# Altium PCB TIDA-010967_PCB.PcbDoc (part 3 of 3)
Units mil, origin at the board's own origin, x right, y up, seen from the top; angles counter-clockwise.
Board outline 2322.7 x 960 mil, 2 copper layers (Top Layer, Bottom Layer), stack 44.731 mil thick; 178 components, 80 nets, 496 pads, 399 vias.
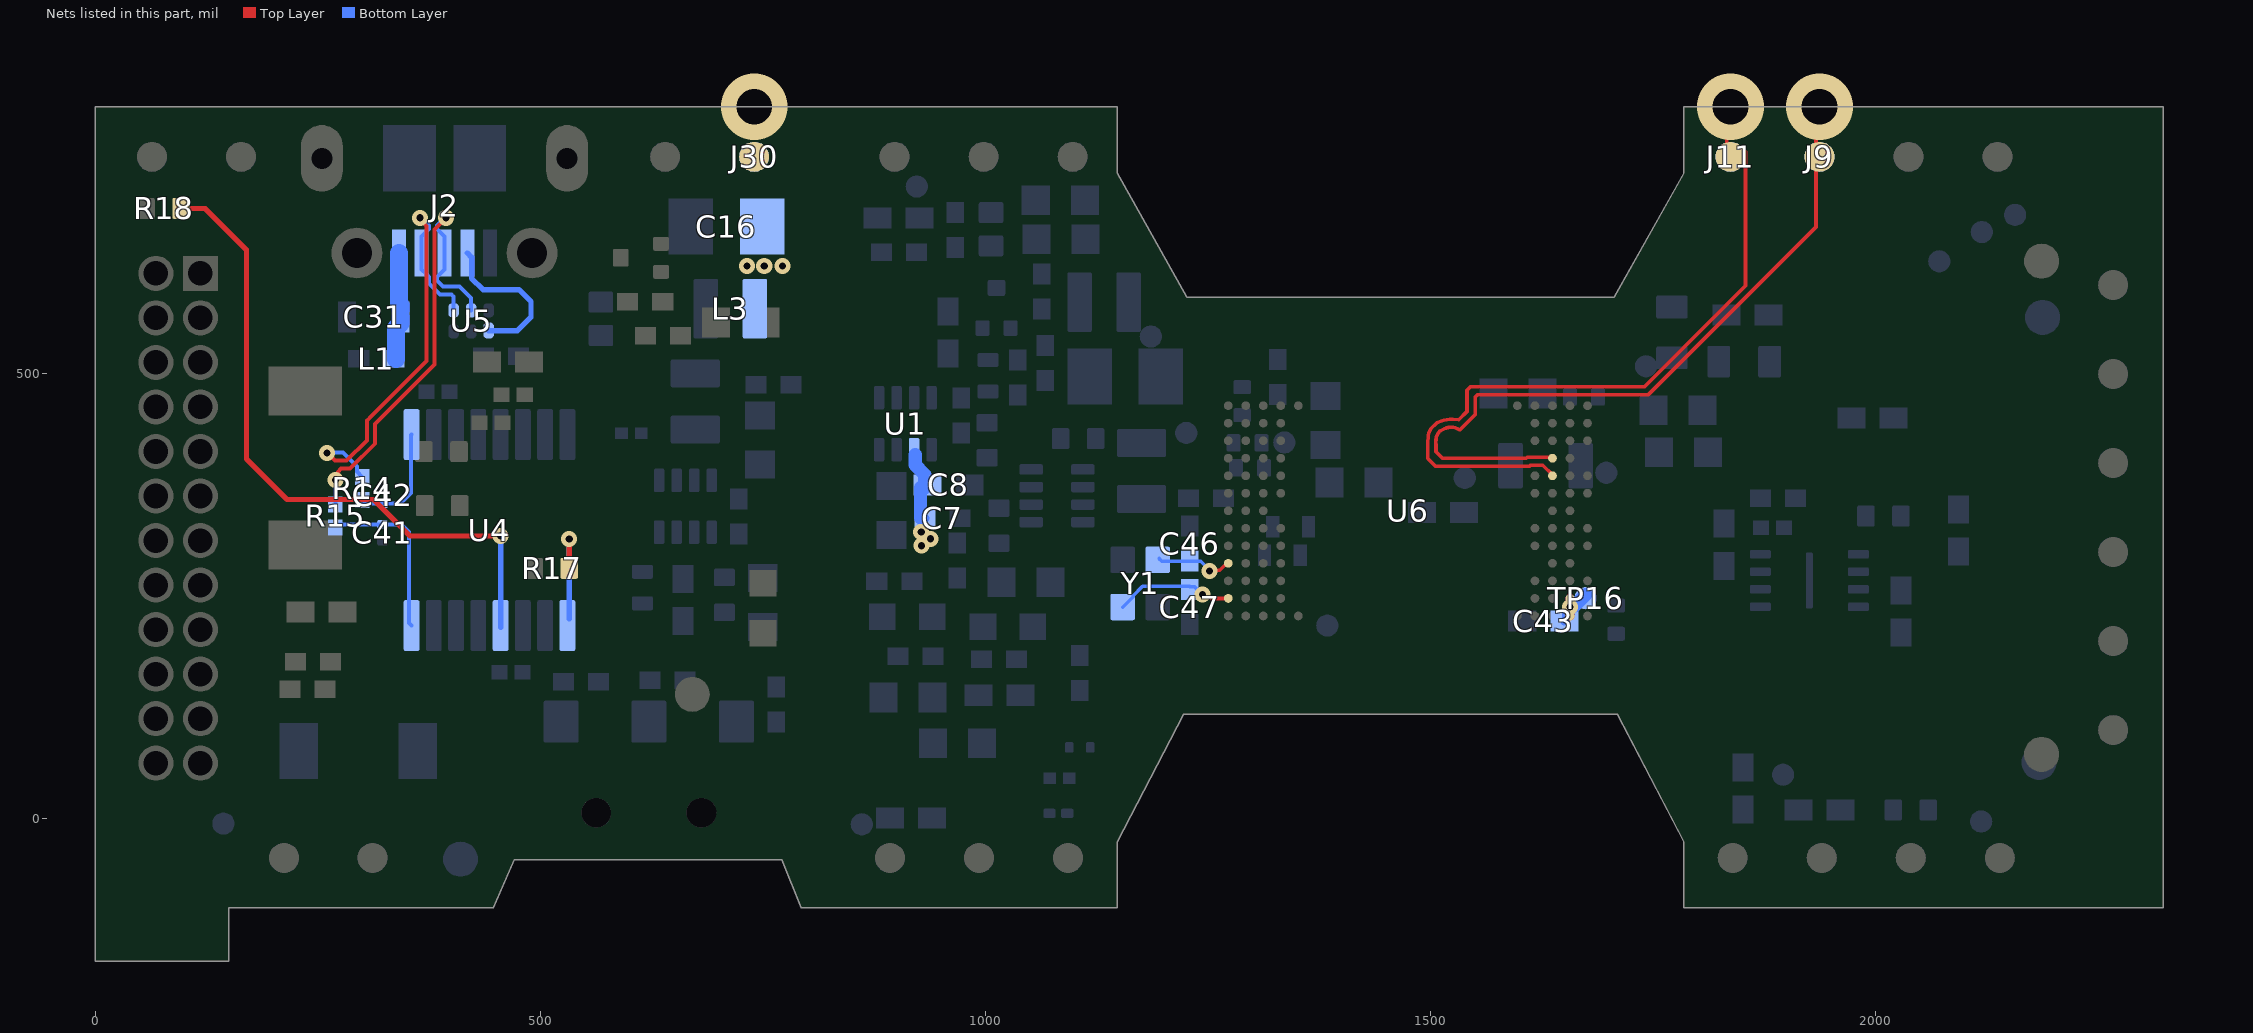
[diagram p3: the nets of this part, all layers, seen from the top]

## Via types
v1: diameter 18, hole 8, Top Layer to Bottom Layer, tented both sides, 370 vias
v2: diameter 75, hole 40, Top Layer to Bottom Layer, 26 vias
v3: diameter 118.11, hole 118.11, Top Layer to Bottom Layer, tented both sides, 3 vias

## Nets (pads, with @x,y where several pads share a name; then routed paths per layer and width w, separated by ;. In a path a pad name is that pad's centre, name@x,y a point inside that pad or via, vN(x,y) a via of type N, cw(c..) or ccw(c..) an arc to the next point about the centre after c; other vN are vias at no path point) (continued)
UART_RX: R18.2 U4.4 | length 751.9
  Top Layer w6: R18.2@96.28,685.75 123.3,685.75 169.77,639.28 169.77,404.28 215.3,358.76 312.41,358.76 353.34,317.83 v1(455.27,317.83)
  Bottom Layer w6: U4.4@455.22,215.01 455.22,317.79 v1(455.27,317.83)
UART_TX: R17.2 U4.1 | length 127.5
  Top Layer w6: R17.2@532.28,281.48 v1(532.28,314.31)
  Bottom Layer w6: v1@530.47,310.91 v1@532.28,312.72 ; U4.1@532.28,224.8 v1@532.28,312.72 ; v1(532.28,314.31) v1@532.28,312.72 ; v1@534.15,314.59 v1@532.28,312.72
UARTA_RX: J11.1 U6.J3 | length 823.4
  Top Layer w4: U6.J3@1636.7,385.49 1636.7,386.44 1625.73,397.41 1612.08,397.41 1610.97,396.3 1505.25,396.3 1496.65,404.9 1496.65,418.75 1496.66,422.97 cw(c1522.66,422.94) 1497,427.16 1497.29,429.55 1497.29,431.02 1497.73,433.18 1500.04,438.15 1506.71,444.82 1512.87,447.12 1514.85,447.74 cw(c1522.66,422.94) 1524.43,448.88 1531.56,448.39 1540.75,457.58 1540.75,481.55 1544.86,485.67 1740.26,485.67 1853.55,598.95 1853.55,749.18 1853.44,749.28 ; J11.1@1832.7,743.75 v2@1832.7,800
  other v2: 1836.65,800
UARTA_TX: J9.1 U6.K3 | length 825.4
  Top Layer w4: U6.K3@1636.27,405.12 1635.1,406.29 1631.56,406.29 1631.44,406.41 1608.35,406.41 1607.24,405.3 1513.17,405.3 1507.08,411.39 1505.91,412.56 1505.91,420 cw(c1522.66,422.94) 1505.91,425.87 1506.29,429.01 1508.43,433.58 1509.04,434.42 1510.44,435.82 1515.01,438.12 cw(c1522.66,422.94) 1532.15,437.04 1532.58,437.04 1532.94,437.05 1549.75,453.85 1549.75,473.68 1552.73,476.67 1744.5,476.67 1932.74,664.9 1932.74,743.75 1932.74,796.09 v2(1936.65,800)
USB_5V: C31.2 J2.1 L1.1 | length 117.3
  Bottom Layer w15: L1.1@335.25,516.74 L1.1@337.06,518.55
  Bottom Layer w20: L1.1@337.74,516.29 337.74,551.37 342.8,556.43 C31.2@342.8,563.93 ; J2.1@341.05,635.69 341.05,579.04 342.8,577.29 C31.2@342.8,571.43
USB_DM: J2.2 R14.1 U5.4 | length 527.7
  Top Layer w4.5: v1(260.3,411.23) 269.14,402.39 282.29,402.39 305.06,425.16 305.06,447.27 310.33,452.54 371.92,514.13 371.92,666.05 364.83,673.14 v1(364.83,675.22)
  Bottom Layer w4.5: v1(260.3,411.23) 260.71,411.64 278.3,411.64 293.82,396.12 293.82,390.12 R14.1@299.76,384.18 ; v1(364.83,675.22) 366.14,675.22 374.93,666.42 374.93,662.69 366.64,654.4 366.64,616.99 372.26,611.37 374.93,608.73 374.93,601.28 387.03,589.18 399.8,589.18 402.43,586.55 U5.4@402.43,571.28
USB_DP: J2.3 R15.1 U5.5 | length 521.6
  Top Layer w4.5: v1(269.92,380.89) 272.5,383.47 272.5,389.93 275.96,393.39 286.02,393.39 314.06,421.43 314.06,443.54 380.92,510.4 380.92,662.12 v1(394.05,675.27)
  Bottom Layer w4.5: R15.1@269.37,353.37 269.92,353.92 v1(269.92,380.89) ; v1(394.05,675.27) 392.79,675.27 383.93,666.42 383.93,662.69 392.23,654.4 J2.3@392.23,635.69 392.23,616.99 386.6,611.37 383.93,608.73 383.93,605.01 390.76,598.18 403.53,598.18 403.6,598.11 408.8,598.11 421.78,585.13 421.78,571.62 U5.5@422.12,571.28
USB_ID: J2.4 U5.1 | length 179.5
  Bottom Layer w6: J2.4@417.82,635.69 422.69,630.82 422.69,607.22 435.41,594.5 475.94,594.5 489.4,581.04 489.4,563.6 474.29,548.49 U5.1@441.66,548.49
USB_INPUT_3V3: C7.1 C8.2 C16.1 J30.1 L3.2 U1.6 | length 79.1
  Bottom Layer w10: C7.1@929,340.58 C7.1@931.83,337.76
  Bottom Layer w15: U1.6@920.94,409.06 920.94,397.52 931.82,386.65 C8.2@931.82,372.19 ; C7.1@926.81,338.48 C8.2@926.81,372.19
  other v1: 927.83,306.91 938.28,314.7 927.69,322.19 732.02,621.26 751.37,621.26 771.92,621.02
  other v2: 740.07,800
USBDM: C42.2 R14.2 U4.9 | length 124.1
  Bottom Layer w4.5: R14.2@301.23,354.52 301.46,354.29 316.88,354.29 342.61,354.29 354.67,366.35 354.67,431.16 U4.9@355.24,431.73
USBDP: C41.2 R15.2 U4.8 | length 193.4
  Bottom Layer w4.5: R15.2@268.94,330.46 269.39,330.91 343.64,330.91 352.26,322.29 352.26,220.14 U4.8@355.24,217.16
VPP_1P7: C43.1 TP16.1 U6.A2 U6.B2 | length 55
  Top Layer w10: U6.A2@1656.39,228.01 U6.B2@1656.39,247.7
  Bottom Layer w10: C43.1@1650.04,222.13 1652.21,224.29 v1@1652.21,236.65
  Bottom Layer w15: v1@1659.85,238.02 TP16.1@1673.91,252.09
  other v1: 1656.45,238.02
XTALM: C47.2 U6.B10 Y1.1 | length 124.9
  Top Layer w4: v1@1251.82,249.38 1253.59,247.62 U6.B10@1272.35,247.62
  Bottom Layer w4: Y1.1@1153.95,237.93 1165.73,249.71 1165.73,250.86 1176.26,261.4 C47.2@1229.39,261.4 ; C47.2@1229.39,260.93 1234.67,260.93 v1(1243.54,252.06)
XTALP: C46.2 U6.D10 Y1.3 | length 88.3
  Top Layer w4: v1@1251,279.05 1251.25,279.3 1263.07,279.3 1271.01,287.24 U6.D10@1272.59,287.24
  Bottom Layer w4: Y1.3@1194.84,292.6 1197.97,289.47 1241.76,289.47 1251.42,279.81 v1(1251.42,278.38)
pads on no net: FID1.1 FID2.1 FID3.1 FID4.1 FID5.1 FID6.1 J1.5 J1.6 J1.7 J1.8 J1.10 J1.13 J1.14 J1.16 SW1. U4.2 U4.6 U4.7 U4.14 U4.15 U4.16 U6.L3 U6.L4
copper on no net:
  other v3: 75.87,-88.15 2251.57,-27.28 2251.07,726.6

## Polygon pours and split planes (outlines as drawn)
RADAR_1V2 on Bottom Layer "RADAR_1V2_L02_P039" (solid, remove dead copper, pour order 39): 1664.37,427.66 1697.77,427.66 1723.65,427.66 1723.65,413.87 1713.96,404.19 1713.96,370.84 1652.34,370.84 1652.34,420.62
REG_3V3 on Bottom Layer "REG_3V3_L02_P033" (solid, remove dead copper, pour order 33): 904.81,277.66 904.81,257.51 923.51,238.8 923.51,66.76 960.5,66.76 960.5,103.72 976.09,121.77 1013.61,121.98 1013.61,168.41 1013.61,217.62 1017.87,221.87 1017.87,259.62 1035.08,276.82 1035.08,301.5 1065.88,301.5 1065.88,340.97 999.28,340.97 999.28,324.45 952.48,277.66
SW3_3V3 on Bottom Layer "SW3_3V3_L02_P044" (solid, remove dead copper, pour order 44): 643.65,455.15 702.69,455.15 702.69,419.41 692.56,419.41 678.9,405.75 678.9,366.52 665.96,366.52 665.96,405.49 652.04,419.41 643.74,419.41
RADAR_1V8 on Bottom Layer "RADAR_1V8_L02_P041" (solid, remove dead copper, pour order 41): 1356.54,488.31 1317.87,488.31 1317.87,467.23 1277.53,467.23 1277.53,443.63 1347.92,443.63 1356.72,452.43
GND on Bottom Layer "GND_L02_P061" (solid, remove dead copper, pour order 61): -7.41,800 -7.41,-160 2315.29,-160 2315.29,800
USB_INPUT_3V3 on Bottom Layer "USB_INPUT_3V3_L02_P058" (solid, remove dead copper, pour order 58): 917.62,388.33 917.62,303.4 923.44,297.58 949.01,297.58 949.01,388.33
REG_1V8 on Bottom Layer "REG_1V8_L02_P057" (solid, remove dead copper, pour order 57): 1146.03,616.54 1145.78,616.29 1145.78,543.21 1146.78,543.21 1169.47,520.51 1169.47,465.64 1225.85,465.64 1225.85,532.48 1212.91,532.48 1193.17,552.23 1193.17,560.79 1175.96,578 1175.96,616.29
REG_OUT_1V8 on Bottom Layer "REG_OUT_1V8_L02_P055" (solid, remove dead copper, pour order 55): 1090.32,667.74 1091.63,666.43 1091.63,545.6 1125.97,545.6 1130.43,550.05 1130.43,668
REG_OUT_1V8 on Bottom Layer "REG_OUT_1V8_L02_P054" (solid, remove dead copper, pour order 54): 1112.86,445.86 1112.86,406.14 1203.76,406.14 1204.2,406.59 1204.05,406.74 1204.05,446.01
DC_OUT_3V3 on Bottom Layer "DC_OUT_3V3_L02_P045" (solid, remove dead copper, pour order 45): 673.34,608.75 708.65,608.75 708.65,532.93 763.79,477.79 763.79,432.56 724.94,432.56 724.94,451.57 701.6,474.91 642.9,474.91 642.9,578.31
5V_IN_USB on Bottom Layer "5V_IN_USB_L02_P043" (solid, remove dead copper, pour order 43): 736.55,335.44 686.1,335.48 686.1,305.78 719.48,305.78 730,295.26 730,265.43 712.75,248.18 693.24,248.18 693.24,224.84 694.04,224.04 718.81,224.04 718.81,226.28 739.2,246.67 767.88,246.67 767.88,307.08
NetD1_2 on Bottom Layer "NETD1_2_L02_P052" (solid, remove dead copper, pour order 52): 192.27,526.97 311.02,526.97 311.02,497.52 191.97,497.52
USB_INPUT_3V3 on Bottom Layer "USB_INPUT_3V3_L02_P046" (solid, remove dead copper, pour order 46): 723.31,752.95 723.31,534.79 768.85,534.79 782.08,548.02 782.08,752.23
RADAR_1P2_RF on Bottom Layer "RADAR_1P2_RF_L02_P031" (solid, remove dead copper, pour order 31): 1302.05,438.29 1399.72,438.29 1399.72,403.58 1357.84,403.58 1349.45,411.97 1302.19,411.97
RADAR_1V_RF_OUT on Bottom Layer "RADAR_1V_RF_OUT_L02_P032" (solid, remove dead copper, pour order 32): 1305.23,404.9 1305.62,404.51 1349.32,404.51 1359.13,394.69 1400.25,394.69 1400.25,360.47 1363.84,360.47 1340.07,384.24 1305.42,384.24
RADAR_SRAM_1V2 on Bottom Layer "RADAR_SRAM_1V2_L02_P038" (solid, remove dead copper, pour order 38): 1666.18,494.66 1596.91,494.66 1596.91,456.88 1636.7,456.88 1636.7,444.17 1666.55,444.17
SW3_1V8 on Bottom Layer "SW3_1V8_L02_P034" (solid, remove dead copper, pour order 34): 1095.35,359.82 1095.35,345.85 1143.77,345.85 1147.96,341.66 1205.92,341.66 1205.92,375.92 1205.05,376.78 1142.61,376.78 1125.77,359.95
5V_IN_USB on Bottom Layer "5V_IN_USB_L02_P028" (solid, remove dead copper, pour order 28): 193.18,-45.67 252.18,-45.67 252.18,153.48 252.18,209.9 193.18,209.9
USB_INPUT_3V3 on Top Layer "USB_INPUT_3V3_L01_P049" (solid, remove dead copper, pour order 49): 721.81,632.03 855.98,632.03 878.57,609.44 878.57,429.5 947.48,360.6 947.48,296.98 915.56,296.98 915.56,332.21 848.32,399.45 848.32,415.17 832.22,432.14 831.87,464.05 845.23,479.12 845.23,602.32 721.81,602.92
5V_IN_USB on Top Layer "5V_IN_USB_L01_P042" (solid, remove dead copper, pour order 42): 233.71,150.17 233.79,150.1 233.79,126.72 519.92,126.72 703.07,309.87 771.2,309.87 771.2,245.48 694.18,245.48 548.84,100.14 192.4,100.14 192.4,154.19
GND on Top Layer "GND_L01_P063" (solid, remove dead copper, pour order 63): 1598,469.39 1597.76,469.15 1558.07,469.15 1558.07,451.58 1558.07,425 1589.1,425 1589.7,424.4 1601.01,435.71 1601.01,469.27 1601.49,469.75
GND on Top Layer "GND_L01_P060" (solid, remove dead copper, pour order 60): 0,800 0,-160 2322.7,-160 2322.7,800
NetD1_2 on Top Layer "NETD1_2_L01_P053" (solid, remove dead copper, pour order 53): 192.12,528.15 281.04,528.15 281.04,452.91 191.46,452.91
REG_OUT_1V8 on Top Layer "REG_OUT_1V8_L01_P056" (solid, remove dead copper, pour order 56): 1125.82,405.53 1154.54,405.53 1154.54,529.88 1128.85,555.56 1128.85,632.62 1092.16,632.62 1092.94,631.83 1092.94,534.94 1126.85,501.04
DC_OUT_3V3 on Top Layer "DC_OUT_3V3_L01_P050" (solid, remove dead copper, pour order 50): 715.26,575.16 715.26,510.03 643.41,510.03 643.41,551.13 667.44,575.16
5V_IN_USB on Top Layer "5V_IN_USB_L01_P029" (solid, remove dead copper, pour order 29): 191.82,331.69 191.82,220.19 191.82,105.06 236.91,105.06 237.19,105.35 237.19,180.21 251.51,194.53 251.51,246.4 285.68,280.57 285.68,331.12
RADAR_1V8 on Top Layer "RADAR_1V8_L01_P040" (solid, remove dead copper, pour order 40): 1264.21,474.23 1264.44,474 1264.44,456.58 1281.17,456.58 1281.51,456.92 1282.9,455.54 1282.9,438 1368.16,438 1368.16,474.11

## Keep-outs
Keep-Out Layer:
  text ".Layer_Name" at -1267.26,-2351.64 h60

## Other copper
Top Layer:
  text ".Layer_Name" at -1252.74,-2340.54 h60
Bottom Layer:
  pour cut-out: 1243.38,317.17 1239.29,313.08 1239.29,309.39 1246.08,309.39 1247.92,311.23 1247.92,315.34 1245.87,317.39
  text ".Layer_Name" at -1018.85,-2336.57 h60

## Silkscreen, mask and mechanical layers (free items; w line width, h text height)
Top Overlay:
  lines w10: 201.82,709.94 201.82,709.19 227.06,684.38
  text "RX   TX" at 1826,695.8 h18
  text "GND   3V3" at 611.39,690.75 h18
  text "3V3   GND  1V8" at 874.21,690.24 h18
  text "GPIO5  TCK" at 1993.97,682.42 h18
  text "TX RX" at 243.34,675.58 h18
  text "UARTA" at 1846.58,668.13 h18
  text "USB" at 719.63,661.86 h18
  text "TMS" at 2208.15,579.77 h18 r270
  text "GPIO2" at 2177.66,547.74 h18 r270
  text "SPI CS" at 2206.03,464.81 h18 r270
  text "I2C SDA" at 2177.66,451.19 h18 r270
  text "TEXAS" at 975.77,436.89 h20
  text "INSTRUMENTS" at 917.6,402.96 h20
  text "CLK" at 2209.22,324.65 h18 r270
  text "SCL" at 2177.34,319.13 h18 r270
  text "MOSI" at 2208.51,249.78 h18 r270
  text "MISO" at 2208.51,177.39 h18 r270
  text "For evaluation only;" at 1794.17,171.38 h35
  text "not FCC approved" at 1794.45,133.28 h35
  text "for resale." at 1792.61,96.14 h35
  text "TIDA-010967 Rev.B" at 1790.8,53.2 h40
  text "TDO" at 2009.56,15.69 h18
  text "REG" at 862.45,14 h18
  text "TX    RX  SOP0" at 1819.77,-9.19 h18
  text "5VDC  GND" at 178.77,-9.66 h18
  text "TDI" at 2116.52,-9.83 h18
  text "MODE  GND  NRST" at 862.04,-12.46 h18
  text ".Layer_Name" at -1264.57,-2344.88 h60
Bottom Overlay:
  lines w10: 604.88,307.14 604.88,306.95 614.44,297.39 626.93,297.39 ; 1186.01,583.92 1186.75,583.92 ; 1186.38,583.92 1220.65,549.64 1221.77,549.64 ; 1221.21,549.64 1230.84,549.46 ; 1589.25,443.79 1623.62,443.79
  text "FUNC" at 856.68,68.4 h23
  text "MODE" at 856.82,40.64 h23
  text "FLASHING MODE" at 465.67,4.19 h23
  text ".Layer_Name" at -1018.85,-2336.57 h25
Top Paste:
  text ".Layer_Name" at -1264.57,-2344.88 h60
Bottom Paste:
  text ".Layer_Name" at -1018.85,-2336.57 h60
Top Solder:
  text ".Layer_Name" at -1264.57,-2344.88 h60
  text ".Layer_Name" at -1264.57,-2344.88 h60
Bottom Solder:
  text ".Layer_Name" at -1018.85,-2336.57 h60
Drill Guide:
  text ".Layer_Name" at -1267.26,-2351.64 h60
M1 Board Outline:
  circle w2: c75.83,-88.16 r59.06
  circle w2: c2251.57,-27.15 r59.06
  circle w2: c2251.06,726.6 r59.06
  lines w2: 470.38,-45.81 771.2,-45.81 ; 470.42,-45.84 447,-100 150,-100 150,-160 0,-160 0,800 1147.72,800 1147.73,725.77 1225.82,586 1705.96,586 1784.42,725.77 1784.42,800 2322.7,800 2322.7,-100 1784.42,-100 1784.42,-25.77 1709.51,117.74 1222.67,117.74 1147.73,-25.77 1147.72,-100 793,-100 770.94,-45.67 ; 811.59,202.07 811.59,224.33 834.61,224.33 ; 811.64,202.02 834.66,202.02 ; 812.14,784.22 812.14,767.57 836.23,767.57 836.23,784.24 812.16,784.24 ; 834.66,202.17 834.66,224.29 ; 833,-85.22 833,-45.86 812.11,-45.86 812.11,-85.21 812.13,-85.23 833,-85.23 ; 833,-85.23 833,-85.23 ; 787.23,357.01 834.15,357.01 834.15,400.92 787.23,400.92 787.23,357.01 ; 810.44,486.64 834.74,486.64 834.74,516.84 810.44,516.84 810.44,486.64 ; 810.63,276.77 834.14,276.77 834.14,294.1 810.63,294.1 810.63,276.77 ; 811.87,574.1 835.25,574.1 835.25,589.41 811.9,589.41 811.87,574.1 ; 812.13,719.77 836.79,719.77 836.79,736.24 812.11,736.24 812.13,719.77 ; 814.24,9.72 830.96,9.72 830.96,23.86 814.24,23.86 814.24,9.72
  text ".Layer_Name" at -1273.87,-2274.95 h40
M3 3D STEP Top:
  lines w0.5: 685.19,-354.85 685.19,1023.11 ; 685.19,-354.85 724.56,-354.85 ; 685.19,-354.85 724.56,-354.85 ; 685.19,-354.85 685.19,-453.27 2161.56,-453.27 ; 685.19,1023.11 685.19,1160.9 2161.56,1160.9 ; 685.19,1023.11 724.56,1023.11 ; 685.19,1023.11 724.56,1023.11 ; 724.56,-354.85 ccw(c783.61,-354.85) 842.67,-354.85 ; 724.56,-354.85 cw(c783.61,-354.85) 825.37,-313.09 ; 724.56,-354.85 cw(c783.61,-354.85) 825.37,-313.09 ; 724.56,-354.85 ccw(c783.61,-354.85) 842.67,-354.85 ; 724.56,1023.11 ccw(c783.61,1023.11) 842.67,1023.11 ; 724.56,1023.11 cw(c783.61,1023.11) 842.67,1023.11 ; 724.56,1023.11 cw(c783.61,1023.11) 842.67,1023.11 ; 724.56,1023.11 ccw(c783.61,1023.11) 842.67,1023.11 ; 825.37,-313.09 cw(c783.61,-354.85) 842.67,-354.85 ; 825.37,-313.09 cw(c783.61,-354.85) 842.67,-354.85 ; 825.37,-313.09 882.04,-256.42 ; 825.37,-313.09 882.04,-256.42 ; 882.04,-256.42 882.04,924.68 2063.14,924.68 2063.14,-256.42 882.04,-256.42 ; 1452.59,314.13 1452.59,316.63 ; 1452.59,314.13 1490.09,314.13 ; 1452.59,314.13 1452.59,316.63 ; 1452.59,314.13 1490.09,314.13 ; 1452.59,316.63 1452.59,351.63 ; 1452.59,316.63 1453.59,316.63 ; 1452.59,316.63 1453.59,316.63 ; 1452.59,316.63 1452.59,351.63 ; 1452.59,316.63 1453.59,316.63 ; 1452.59,316.63 1453.59,316.63 ; 1452.59,351.63 1452.59,355.13 ; 1452.59,351.63 1453.59,351.63 ; 1452.59,351.63 1453.59,351.63 ; 1452.59,351.63 1452.59,355.13 ; 1452.59,351.63 1453.59,351.63 ; 1452.59,351.63 1453.59,351.63 ; 1452.59,355.13 1490.09,355.13 ; 1452.59,355.13 1490.09,355.13 ; 1453.59,316.63 cw(c1455.09,316.63) 1456.15,317.69 ; 1453.59,316.63 ccw(c1455.09,316.63) 1456.59,316.63 ; 1453.59,316.63 cw(c1455.09,316.63) 1456.15,317.69 ; 1453.59,316.63 ccw(c1455.09,316.63) 1456.59,316.63 ; 1453.59,351.63 cw(c1455.09,351.63) 1456.59,351.63 ; 1453.59,351.63 ccw(c1455.09,351.63) 1456.59,351.63 ; 1453.59,351.63 cw(c1455.09,351.63) 1456.59,351.63 ; 1453.59,351.63 ccw(c1455.09,351.63) 1456.59,351.63 ; 1456.15,317.69 cw(c1455.09,316.63) 1456.59,316.63 ; 1456.15,317.69 cw(c1455.09,316.63) 1456.59,316.63 ; 1456.15,317.69 1457.59,319.13 ; 1456.15,317.69 1457.59,319.13 ; 1456.15,317.69 1457.59,319.13 ; 1456.15,317.69 1457.59,319.13 ; 1457.59,319.13 1457.59,349.13 ; 1457.59,319.13 1487.59,319.13 ; 1457.59,319.13 1457.59,349.13 ; 1457.59,319.13 1487.59,319.13 ; 1457.59,349.13 1487.59,349.13 ; 1457.59,349.13 1487.59,349.13 ; 1487.59,319.13 1487.59,349.13 ; 1487.59,319.13 1487.59,349.13 ; 1490.09,314.13 1490.09,315.13 ; 1490.09,314.13 1490.09,315.13 ; 1490.09,314.13 1493.59,314.13 ; 1490.09,314.13 1490.09,315.13 ; 1490.09,314.13 1490.09,315.13 ; 1490.09,314.13 1493.59,314.13 ; 1490.09,315.13 cw(c1490.09,316.63) 1491.59,316.63 ; 1490.09,315.13 ccw(c1490.09,316.63) 1491.59,316.63 ; 1490.09,315.13 cw(c1490.09,316.63) 1491.59,316.63 ; 1490.09,315.13 ccw(c1490.09,316.63) 1491.59,316.63 ; 1490.09,353.13 cw(c1490.09,351.63) 1491.59,351.63 ; 1490.09,353.13 ccw(c1490.09,351.63) 1491.59,351.63 ; 1490.09,353.13 cw(c1490.09,351.63) 1491.59,351.63 ; 1490.09,353.13 ccw(c1490.09,351.63) 1491.59,351.63 ; 1490.09,353.13 1490.09,355.13 ; 1490.09,353.13 1490.09,355.13 ; 1490.09,353.13 1490.09,355.13 ; 1490.09,353.13 1490.09,355.13 ; 1490.09,355.13 1493.59,355.13 ; 1490.09,355.13 1493.59,355.13 ; 1493.59,314.13 1493.59,355.13 ; 1493.59,314.13 1493.59,355.13 ; 2161.56,-453.27 2161.56,-413.9 ; 2161.56,-453.27 2161.56,-413.9 ; 2161.56,-453.27 2299.36,-453.27 2299.36,1160.9 2161.56,1160.9 ; 2161.56,-413.9 ccw(c2161.56,-354.85) 2220.62,-354.85 ; 2161.56,-413.9 cw(c2161.56,-354.85) 2220.62,-354.85 ; 2161.56,-413.9 cw(c2161.56,-354.85) 2220.62,-354.85 ; 2161.56,-413.9 ccw(c2161.56,-354.85) 2220.62,-354.85 ; 2161.56,1082.16 ccw(c2161.56,1023.11) 2220.62,1023.11 ; 2161.56,1082.16 cw(c2161.56,1023.11) 2220.62,1023.11 ; 2161.56,1082.16 cw(c2161.56,1023.11) 2220.62,1023.11 ; 2161.56,1082.16 ccw(c2161.56,1023.11) 2220.62,1023.11 ; 2161.56,1082.16 2161.56,1160.9 ; 2161.56,1082.16 2161.56,1160.9
  text ".Layer_Name" at -1267.26,-2351.64 h60
M4 3D STEP Bottom:
  lines w0.5: 583.6,-328.9 583.6,-427.32 2059.98,-427.32 ; 583.6,-328.9 622.97,-328.9 ; 583.6,-328.9 622.97,-328.9 ; 583.6,-328.9 583.6,1049.06 ; 583.6,1049.06 622.97,1049.06 ; 583.6,1049.06 622.97,1049.06 ; 583.6,1049.06 583.6,1186.85 2059.98,1186.85 ; 622.97,-328.9 ccw(c682.03,-328.9) 741.08,-328.9 ccw(c682.03,-328.9) 723.78,-287.14 ; 622.97,-328.9 cw(c682.03,-328.9) 723.78,-287.14 ; 622.97,1049.06 ccw(c682.03,1049.06) 741.08,1049.06 ccw(c682.03,1049.06) 622.97,1049.06 ; 723.78,-287.14 780.45,-230.47 ; 723.78,-287.14 780.45,-230.47 ; 780.45,-230.47 1961.55,-230.47 1961.55,950.63 780.45,950.63 780.45,-230.47 ; 1351,340.08 1388.5,340.08 ; 1351,340.08 1351,342.58 ; 1351,340.08 1388.5,340.08 ; 1351,340.08 1351,342.58 ; 1351,342.58 1352,342.58 ; 1351,342.58 1352,342.58 ; 1351,342.58 1351,377.58 ; 1351,342.58 1352,342.58 ; 1351,342.58 1352,342.58 ; 1351,342.58 1351,377.58 ; 1351,377.58 1352,377.58 ; 1351,377.58 1352,377.58 ; 1351,377.58 1351,381.08 ; 1351,377.58 1352,377.58 ; 1351,377.58 1352,377.58 ; 1351,377.58 1351,381.08 ; 1351,381.08 1388.5,381.08 ; 1351,381.08 1388.5,381.08 ; 1352,342.58 ccw(c1353.5,342.58) 1355,342.58 ; 1352,342.58 cw(c1353.5,342.58) 1354.56,343.64 ; 1352,342.58 ccw(c1353.5,342.58) 1355,342.58 ; 1352,342.58 cw(c1353.5,342.58) 1354.56,343.64 ; 1352,377.58 ccw(c1353.5,377.58) 1355,377.58 ; 1352,377.58 cw(c1353.5,377.58) 1355,377.58 ; 1352,377.58 ccw(c1353.5,377.58) 1355,377.58 ; 1352,377.58 cw(c1353.5,377.58) 1355,377.58 ; 1354.56,343.64 cw(c1353.5,342.58) 1355,342.58 ; 1354.56,343.64 cw(c1353.5,342.58) 1355,342.58 ; 1354.56,343.64 1356,345.08 ; 1354.56,343.64 1356,345.08 ; 1354.56,343.64 1356,345.08 ; 1354.56,343.64 1356,345.08 ; 1356,345.08 1386,345.08 ; 1356,345.08 1356,375.08 ; 1356,345.08 1386,345.08 ; 1356,345.08 1356,375.08 ; 1356,375.08 1386,375.08 ; 1356,375.08 1386,375.08 ; 1386,345.08 1386,375.08 ; 1386,345.08 1386,375.08 ; 1388.5,340.08 1392,340.08 ; 1388.5,340.08 1388.5,341.08 ; 1388.5,340.08 1388.5,341.08 ; 1388.5,340.08 1392,340.08 ; 1388.5,340.08 1388.5,341.08 ; 1388.5,340.08 1388.5,341.08 ; 1388.5,341.08 ccw(c1388.5,342.58) 1390,342.58 ; 1388.5,341.08 cw(c1388.5,342.58) 1390,342.58 ; 1388.5,341.08 ccw(c1388.5,342.58) 1390,342.58 ; 1388.5,341.08 cw(c1388.5,342.58) 1390,342.58 ; 1388.5,379.08 ccw(c1388.5,377.58) 1390,377.58 ; 1388.5,379.08 cw(c1388.5,377.58) 1390,377.58 ; 1388.5,379.08 ccw(c1388.5,377.58) 1390,377.58 ; 1388.5,379.08 cw(c1388.5,377.58) 1390,377.58 ; 1388.5,379.08 1388.5,381.08 ; 1388.5,379.08 1388.5,381.08 ; 1388.5,379.08 1388.5,381.08 ; 1388.5,379.08 1388.5,381.08 ; 1388.5,381.08 1392,381.08 ; 1388.5,381.08 1392,381.08 ; 1392,340.08 1392,381.08 ; 1392,340.08 1392,381.08 ; 2059.98,-427.32 2197.77,-427.32 2197.77,1186.85 2059.98,1186.85 ; 2059.98,-427.32 2059.98,-387.95 ; 2059.98,-427.32 2059.98,-387.95 ; 2059.98,-387.95 ccw(c2059.98,-328.9) 2119.03,-328.9 ccw(c2059.98,-328.9) 2059.98,-387.95 ; 2059.98,1108.11 ccw(c2059.98,1049.06) 2119.03,1049.06 ccw(c2059.98,1049.06) 2059.98,1108.11 ; 2059.98,1108.11 2059.98,1186.85 ; 2059.98,1108.11 2059.98,1186.85
  text ".Layer_Name" at -1267.26,-2351.64 h60
M5 Assembly Top:
  lines w10: -2136.26,-2423.31 4463.74,-2423.31 ; -2136.26,-2219.98 4465.74,-2219.98 ; -2136.26,-2016.65 -2136.26,-2626.65 1868.74,-2626.65 4465.74,-2626.65 4465.74,-2016.65 -2135.76,-2016.65 -2135.76,-2626.65 -560.26,-2626.65 ; 328.74,-2626.65 328.74,-2016.65 ; 1595.74,-2219.98 1595.74,-2016.65 ; 2435.74,-2219.98 2435.74,-2016.65 ; 3057.74,-2633.15 3057.74,-2430.31
  text "COMPONENTS MARKED 'DNP' SHOULD NOT BE POPULATED." at -1037.74,2616.59 h60
  text "ASSEMBLY VARIANT:" at -1038.24,2501.09 h60
  text ".VariantName" at -2.24,2501.09 h60
  text "PCB VIEWED FROM TOP SIDE" at -2072.76,-2148.81 h60
  text "BOARD #:" at 403.74,-2148.81 h60
  text ".PRJ_Number" at 949.24,-2148.81 h60
  text "REV:" at 1793.74,-2148.81 h60
  text ".PCB_Rev" at 2085.24,-2148.81 h60
  text "SVN REV:" at 2631.74,-2148.81 h60
  text ".VersionControl_RevNumber" at 3137.74,-2148.81 h60
  text "Assembly Layer Top" at -1277.26,-2348.15 h60
  text "TID #:" at 403.74,-2352.15 h60
  text ".TID" at 949.24,-2352.15 h60
  text "PLOT NAME =" at -2072.76,-2557.48 h60
  text ".plot_File_Name" at -1267.26,-2557.48 h60
  text "GENERATED    :" at 405.74,-2557.48 h60
  text ".Print_Date" at 1275.24,-2557.48 h60
  text ".Print_Time" at 2004.24,-2557.48 h60
  text "TEXAS INSTRUMENTS" at 3268.74,-2557.48 h60
M6 Assembly Bottom:
  lines w10: -2136.76,-2220.48 4465.24,-2220.48 ; -2134.76,-2423.81 4465.24,-2423.81 ; -728.76,-2633.65 -728.76,-2430.81 ; -106.76,-2220.48 -106.76,-2017.15 ; 733.24,-2220.48 733.24,-2017.15 ; 2000.24,-2627.15 2000.24,-2017.15 ; 2889.24,-2627.15 4464.74,-2627.15 4464.74,-2017.15 -2136.76,-2017.15 -2136.76,-2627.15 460.24,-2627.15 4465.24,-2627.15 4465.24,-2017.15
  text "COMPONENTS MARKED 'DNP' SHOULD NOT BE POPULATED." at 4462.31,-1794.1 h60
  text ".VariantName" at 3418.31,-1910.1 h60
  text "ASSEMBLY VARIANT:" at 4457.31,-1910.1 h60
  text ".VersionControl_RevNumber" at -808.76,-2149.31 h60
  text "SVN REV:" at -302.76,-2149.31 h60
  text ".PCB_Rev" at 243.74,-2149.31 h60
  text "REV:" at 535.24,-2149.31 h60
  text ".PRJ_Number" at 1379.74,-2149.31 h60
  text "BOARD #:" at 1925.24,-2149.31 h60
  text "PCB VIEWED FROM BOTTOM SIDE" at 4401.74,-2149.31 h60
  text "Assembly Bottom Layer" at 4040.74,-2338.15 h60
  text ".TID" at 1379.74,-2352.65 h60
  text "TID #:" at 1925.24,-2352.65 h60
  text "TEXAS INSTRUMENTS" at -939.76,-2557.98 h60
  text ".Print_Time" at 324.74,-2557.98 h60
  text ".Print_Date" at 1053.74,-2557.98 h60
  text "GENERATED    :" at 1923.24,-2557.98 h60
  text ".plot_File_Name" at 3596.24,-2557.98 h60
  text "PLOT NAME =" at 4401.74,-2557.98 h60
M9 Title Sheet:
  lines w10: 164.24,-2826.65 164.24,-2626.65 ; 164.24,6473.35 164.24,6673.35 ; 2664.24,-2826.65 2664.24,-2626.65 ; 2664.24,6473.35 2664.24,6673.35
  text "1" at -1104.43,6543.35 h70
  text "2" at 1391.24,6543.35 h70
  text ".Layer_Name" at -1257.96,-2358.63 h60
  text "1" at -1104.43,-2756.65 h70
  text "2" at 1391.24,-2756.65 h70
M10 Fab Notes:
  drawing of 251 lines, arcs and shapes, not listed
  text "3" at 3880.58,6543.35 h70
  text "4" at 6387.25,6543.35 h70
  text "5" at 8886.24,6543.35 h70
  text "6" at 11391.24,6543.35 h70
  text "A" at -2260.76,5400.35 h70
  text "A" at 12539.24,5400.35 h70
  text "DESIGN INFORMATION" at 10537.75,4863.03 h60
  text "4.0" at 10932.23,4733.63 h60
  text "MIN. TRACK WIDTH:" at 9893.2,4730.9 h60
  text "MIL" at 11144.2,4730.9 h60
  text "4.0" at 10929.69,4614.25 h60
  text "MIN. CLEARANCE:" at 9893.2,4606.77 h60
  text "MIL" at 11144.2,4606.77 h60
  text "MIN. VIA PAD SIZE:" at 9893.2,4482.65 h60
  text "18" at 10915.88,4475.28 h60
  text "MIL" at 11166.74,4473.85 h60
  text "EXTERNAL" at 11414.34,4355.34 h60
  text "0.127mm (5.0MIL)" at 10588.2,4352.75 h60
  text "MINIMUM ANNULAR RING" at 9563.96,4344.53 h60
  text "PER" at 9763.96,4234.4 h60
  text "IPC-D-275 CLASS 2 LEVEL C" at 9983.96,4234.4 h60
  text "MIL, HOLES" at 11472.2,4133.92 h60
  text "+/-" at 11079.74,4125.34 h60
  text "+/-" at 11933.74,4125.34 h60
  text "REGISTRATION TOLERANCES:" at 9563.96,4124.27 h60
  text "METAL" at 10763.74,4124.27 h60
  text "5" at 11339.94,4124.27 h60
  text "3" at 12172.94,4124.27 h60
  text "MIL" at 12289.2,4124.27 h60
  text "HOLE SIZE TOLERANCE (UNLESS OTHERWISE SPECIFIED):" at 9563.96,4025.96 h60
  text "+/-" at 11933.74,4023.08 h60
  text "3" at 12172.94,4022.02 h60
  text "MIL" at 12289.2,4022.02 h60
  text "MATERIAL:" at 9489.2,3884.37 h60
  text "FR-4 High Tg" at 10475.64,3755.85 h60
  text "X" at 11217.74,3750.85 h60
  text "REFER STACK-UP" at 11718.59,3750.26 h55
  text "FR-408" at 9910.2,3743.34 h60
  text "OTHER" at 11398.2,3743.34 h60
  text "X" at 11388.74,3602.86 h60
  text "62 MIL (1.6mm) +/-10%" at 10230.3,3600.31 h60
  text "45.531 MIL +/-10%" at 11810.74,3593.85 h45
  text "THICKNESS:" at 9563.96,3592.09 h60
  text "OTHER" at 11515.2,3592.09 h60
  text "TOLERANCE:" at 9563.96,3453.78 h60
  text "X" at 10412.2,3453.78 h60
  text "ANSI IPC-6012 TYPE 3 CLASS 2" at 10590.21,3453.78 h60
  text "OTHER +/-" at 10590.2,3309.59 h60
  text "BOW & TWIST:" at 9563.96,3164.4 h60
  text "X" at 10412.2,3164.4 h60
  text "ANSI IPC-6012 TYPE 3 CLASS 2" at 10590.21,3164.4 h60
  text "B" at -2260.76,3020.35 h70
  text "B" at 12539.24,3020.35 h70
  text "OTHER +/-" at 10590.2,3017.7 h60
  text "DRILLING:" at 9489.2,2887.08 h60
  text "NC_DRILL FILES" at 11250.2,2781.89 h60
  text "REFERENCE:" at 9563.96,2777.96 h60
  text "X" at 10221.2,2777.86 h60
  text "AS SHOWN" at 10399.2,2777.96 h60
  text "X" at 11122.2,2777.96 h60
  text "OTHER" at 11548.2,2635.7 h60
  text "PTH COPPER THICKNESS:" at 9563.64,2632.18 h60
  text "X" at 10702.88,2632.18 h60
  text "20-30 um" at 10830.87,2632.18 h60
  text "NOTES:" at 2136.8,2578.1 h60
  text "BOARD FINISH:" at 9489.2,2484.58 h60
  text "1. BOARD SHALL MEET THE REQUIREMENTS OF UL-796E WITH FLAMMABILITY RATING OF MINIMUM 94V-0. UL LOGO," at 2163.55,2432.27 h60
  text "SILKSCREEN:" at 9644.42,2374.45 h60
  text "X" at 10602.2,2374.45 h60
  text "TOP" at 10719.2,2374.45 h60
  text "X" at 11112.2,2374.45 h60
  text "BOTTOM" at 11230.2,2374.45 h60
  text "MANUFACTURER'S IDENTIFICATION AND DATE CODE LETTER SHALL BE RENDERED IN SILKSCREEN." at 2270.28,2333.27 h60
  text "SILKSCREEN COLOR:" at 9644.42,2219.26 h60
  text "X" at 10601.2,2219.26 h60
  text "WHITE" at 10719.2,2219.26 h60
  text "OTHER" at 11230.2,2219.26 h60
  text "2. VENDOR MAY ADJUST SOLDERMASK WHEREVER SOLDERMASK PADS ARE THE SAME SIZE (1:1) AS PER THE MANUFACTURING CAPABILITIES" at 2156.57,2207.49 h60
  text "AND ALL OTHER SOLDER MASK PADS SHALL NOT BE MODIFIED, PROVIDED NO ADJACENT COPPER IS EXPOSED AND NO CONFLICT IS PRODUCED" at 2263.3,2108.49 h60
  text "GREEN" at 10850.2,2075.82 h60
  text "X" at 11319.37,2076.21 h60
  text "OTHER" at 11468.2,2075.82 h60
  text "RED" at 11840.74,2075.82 h60
  text "SOLDER RESIST COLOR:" at 9644.42,2068.95 h60
  text "WITH ANY STATED \"VIA TENTING/COVERING\" REQUIREMENTS." at 2263.3,2015.21 h60
  text "MATTE" at 10850.2,1921.56 h60
  text "SEMI-GLOSS" at 11467.74,1920.93 h60
  text "3. MANUFACTURER'S IDENTIFICATION,DATECODE LETTER SHALL BE SILKSCREENED ON SOLDER SIDE OF THE BOARD." at 2160.24,1897.11 h60
  text "4. TRACE WIDTH SHOULD BE ACCURATELY ETCHED. MAX TOLERANCE +/- 1 MIL." at 2155.29,1760.78 h60
  text "IMMERSION GOLD (ENIG)" at 10550.2,1748.79 h60
  text "ENEPIG" at 11887.74,1741.57 h60
  text "SURFACE FINISH:" at 9489.2,1740.57 h60
  text "X" at 10373.69,1737.09 h60
  text "5. LAYER TO LAYER REGISTRATION SHALL BE WITHIN +/-2 MIL." at 2162.35,1636.67 h60
  text "IMM. TIN/SILVER OR EQUIV" at 9818.74,1603.26 h60
  text "OTHER" at 11250.2,1599.32 h60
  text "6. REFER IMPEDANCE TABLE FOR IMPEDANCE CONTROL TRACES ON LAYER 1." at 2153.38,1515.8 h60
  text "ARRAY/PANEL:" at 9489.2,1443.94 h60
  text "CUT AND TRIM PER M1 BOARD OUTLINE" at 10550.2,1435.72 h60
  text "7. FOR ACCURACY OF THE ANTENNA DIMENSION, NEED TO BE MEASURE THE  ANTENNA DIMENSIONS ON ONE BOARD" at 2151.19,1364.04 h60
  text "N.C. ROUTE" at 10550.2,1299.75 h60
  text "V. SCORE" at 11416.2,1299.75 h60
  text "X" at 11233.19,1293.81 h60
  text "8. ALL VIAS ARE TENTED ON BOTH SIDES UNLESS OTHERWISE SOLDER MASK OPENED IN GERBER." at 2144.77,1251.36 h60
  text "CERTIFICATION:" at 9489.2,1170.63 h60
  text "MATERIALS AND WORKMANSHIP FOR ALL PCBS" at 10214.2,1170.63 h60
  text "9. VIA HOLE OFFSET SHALL BE WITHIN 1MILS OF ITS ORIGINAL LOCATION" at 2148.7,1135.75 h60
  text "TO MEET OR EXCEED THE REQUIREMENTS OF:" at 10214.2,1076.56 h60
  text "X" at 9851.7,947.93 h60
  text "ANSI IPC-A-600F CLASS ->" at 9979.7,947.93 h60
  text "X" at 11627.7,947.93 h60
  text "2" at 11737.7,947.93 h60
  text "1" at 11422.7,946.44 h60
  text "3" at 12091.7,946.44 h60
  text "X" at 10663.7,800.25 h60
  text "RoHS" at 10791.7,800.25 h60
  text "OTHER" at 11436.1,800.25 h60
  text "PER ORDER" at 11833.16,800.25 h60
  text "ALL BOARDS MUST MEET OR EXCEED UL94-V0 REQUIREMENTS." at 9516.74,646.42 h60
  text "C" at -2260.76,645.35 h70
  text "C" at 12539.24,645.35 h70
  text "PCB MUST BEAR THE UL94V-0 UL REGISTERED MATERIAL ID NUMBER" at 9516.74,530.36 h60
  text "ADDITIONAL REQUIREMENTS:" at 9489.2,360.93 h60
  text "MICROSECTION:" at 9563.96,253.81 h60
  text "YES" at 10469.7,253.81 h60
  text "REQUIRED" at 11331.2,109.47 h60
  text "BARE BOARD ELEC. TEST:" at 9563.96,106.62 h60
  text "NONE" at 10869.7,106.62 h60
  text "X" at 11213.2,106.62 h60
  text "PER ORDER" at 11923.2,106.62 h60
  text "XX MIL VIAS REQUIRE NON-CONDUCTIVE FILL AND PLANARIZE" at 9747.74,-39.15 h59
  text "XX MIL VIAS REQUIRE CONDUCTIVE FILL AND PLANARIZE" at 9738.74,-198.15 h60
  text "OUTER XX MIL TRACES REQUIRE 50 OHM SINGLE-ENDED IMPEDANCE" at 9733.88,-341.05 h58
  text "LAYER 1 & 6 (INNER LAYERS) XX MIL WIDE, XX MIL SPACE / TRACES REQUIRE 100 OHM DIFFERENTIAL IMPEDANCE" at 9772.74,-591.15 h60
  text "PROJECT TITLE:" at 9499.24,-1215.65 h45
  text ".PRJ_Title" at 9549.24,-1348.97 h70
  text "DESIGNED FOR:" at 9499.24,-1516.65 h45
  text ".PRJ_Customer" at 9549.24,-1656.65 h70
  text "D" at -2260.76,-1724.65 h70
  text "D" at 12539.24,-1724.65 h70
  text "FILE NAME:" at 9499.24,-1816.65 h45
  text ".PCB_File_Name_No_Path" at 9549.24,-1936.65 h70
  text "Texas Instruments (TI) and/or its licensors do not warrant the accuracy or completeness of this specification" at 4529.74,-2098.49 h45
  text "ENGINEER:" at 9499.24,-2106.65 h45
  text "LAYOUT BY:" at 11004.24,-2106.65 h45
  text "or any information contained therein. TI and/or its licensors do not warrant that this design will meet" at 4484.75,-2211.15 h45
  text ".PRJ_Engineer" at 9549.24,-2261.64 h70
  text ".PCB_Layout" at 11054.74,-2261.64 h70
  text "the specifications, will be suitable for your application or fit for any particular purpose, or will operate in" at 4484.75,-2323.82 h45
  text ".Layer_Name" at -1257.96,-2358.63 h60
  text "ALTIUM DESIGNER VERSION:" at 11004.24,-2416.65 h45
  text "an implementation. TI and/or its licensors do not warrant that the design is production worthy. You should" at 4484.75,-2436.48 h45
  text "completely validate and test your design implementation to confirm the system functionality for your application." at 4529.74,-2549.15 h45
  text ".print_Scale" at 9549.24,-2549.97 h70
  text ".Application_BuildNumber" at 11054.74,-2549.97 h70
  text "3" at 3880.58,-2756.65 h70
  text "4" at 6387.25,-2756.65 h70
  text "5" at 8886.24,-2756.65 h70
  text "6" at 11240.42,-2767 h70
M11 Gerber Information:
  lines w10: -2136.26,-2423.31 4463.74,-2423.31 ; -2136.26,-2219.98 4465.74,-2219.98 ; -2136.26,-2016.65 -2136.26,-2626.65 1868.74,-2626.65 4465.74,-2626.65 4465.74,-2016.65 -2135.76,-2016.65 -2135.76,-2626.65 -560.26,-2626.65 ; 328.74,-2626.65 328.74,-2016.65 ; 1595.74,-2219.98 1595.74,-2016.65 ; 2435.74,-2219.98 2435.74,-2016.65 ; 3057.74,-2633.15 3057.74,-2430.31
  text "ALL ARTWORK VIEWED FROM TOP SIDE" at -2072.76,-2148.81 h60
  text "BOARD #:" at 403.74,-2148.81 h60
  text ".PRJ_Number" at 949.24,-2148.81 h60
  text "REV:" at 1793.74,-2148.81 h60
  text ".PCB_Rev" at 2085.24,-2148.81 h60
  text "SVN REV:" at 2631.74,-2148.81 h60
  text ".VersionControl_RevNumber" at 3137.74,-2148.81 h60
  text "LAYER NAME =" at -2072.76,-2351.64 h60
  text "TID #:" at 403.74,-2352.15 h60
  text ".TID" at 949.24,-2352.15 h60
  text "PLOT NAME =" at -2072.76,-2557.48 h60
  text ".plot_File_Name" at -1267.26,-2557.48 h60
  text "GENERATED    :" at 405.74,-2557.48 h60
  text ".Print_Date" at 1275.24,-2557.48 h60
  text ".Print_Time" at 2004.24,-2557.48 h60
  text "TEXAS INSTRUMENTS" at 3268.74,-2557.48 h60
M12 Stackup:
  drawing of 212 lines, arcs and shapes, not listed
  text "NOTE :" at 5742.51,5800.49 h60
  text "1. THIS IS AN IMPEDANCE CONTROLLED BOARD." at 5926.02,5695.46 h60
  text "2. EXTERNAL LAYER CU THICKNESSES ARE FINISHED THICKNESS AFTER PLATING." at 5926.02,5597.59 h60
  text "6" at 7810.15,5434.9 h60
  text "IMPEDANCE TABLE :" at 6653.76,5419.52 h80
  text "LAYER" at 6152.01,5310.17 h70
  text "TRACE WIDTH" at 6439.21,5309.32 h70
  text "SPACING" at 6924.21,5309.32 h70
  text "IMPEDANCE +/- 10%" at 7259.21,5309.32 h70
  text "REFERENCE LAYER" at 7984.21,5309.32 h70
  text "TOP" at 6219.09,5151.18 h70
  text "4.5 MIL" at 6504.09,5146.18 h65
  text "4.5 MIL" at 6959.09,5146.18 h65
  text "90 OHM" at 7379.09,5146.18 h65
  text "LAYER-2 (GND PLANE)" at 7944.09,5146.18 h65
  text "LAYER STACK-UP :" at 3295.72,720.87 h80
  text "Layer" at 3010.53,463.49 h60
  text "Name" at 3420.45,463.49 h60
  text "Material" at 4350.19,463.49 h60
  text "Thickness" at 5909.73,463.49 h60
  text "Constant" at 6559.57,463.49 h60
  text "Board Layer Stack" at 7129.43,463.49 h60
  text "Top Overlay" at 3420.45,343.49 h60
  text "Top Solder" at 3420.45,223.49 h60
  text "Solder Resist" at 4350.19,223.49 h60
  text "0.40mil" at 5909.73,223.49 h60
  text "4.5" at 6559.57,223.49 h60
  text "1" at 3010.53,103.49 h60
  text "Top Layer" at 3420.45,103.49 h60
  text "1.40mil" at 5909.73,103.49 h60
  text "Dielectric 1" at 3420.45,-16.51 h60
  text "FR-4 High Tg135 (KB-6164)" at 4350.19,-16.51 h60
  text "41.93mil" at 5909.73,-16.51 h60
  text "4.5" at 6559.57,-16.51 h60
  text "2" at 3010.53,-136.51 h60
  text "Bottom Layer" at 3420.45,-136.51 h60
  text "1.40mil" at 5909.73,-136.51 h60
  text "Bottom Solder" at 3420.45,-256.51 h60
  text "Solder Resist" at 4350.19,-256.51 h60
  text "0.40mil" at 5909.73,-256.51 h60
  text "4.5" at 6559.57,-256.51 h60
  text "Bottom Overlay" at 3420.45,-376.51 h60
  text ".Layer_Name" at -1267.26,-2351.64 h60
M13 Component Bodies Top:
  text ".Layer_Name" at -1267.26,-2351.64 h60
M14 Component Bodies Bottom:
  text ".Layer_Name" at -1267.26,-2351.64 h60
M15 Courtyards Top:
  text ".Layer_Name" at -1267.26,-2351.64 h60
M16 Courtyards Bottom:
  text ".Layer_Name" at -1267.26,-2351.64 h60
Drill Drawing:
  circle w10: c-1639.6,4789.77 r33.33
  lines w10: -1672.94,4006.44 -1672.94,4023.11 -1656.27,4039.77 -1672.94,4056.44 -1672.94,4073.11 -1656.27,4073.11 -1639.6,4056.44 -1622.94,4073.11 -1606.27,4073.11 -1606.27,4056.44 -1622.94,4039.77 -1606.27,4023.11 -1606.27,4006.44 -1622.94,4006.44 -1639.6,4023.11 -1656.27,4006.44 -1672.94,4006.44 ; -1672.94,4156.44 -1606.27,4156.44 -1606.27,4223.11 -1672.94,4223.11 -1672.94,4156.44 ; -1672.94,4373.11 -1606.27,4373.11 -1639.6,4306.44 -1672.94,4373.11 ; -1672.94,4473.11 -1656.27,4473.11 -1639.6,4456.44 -1622.94,4473.11 -1606.27,4473.11 -1622.94,4489.77 -1606.27,4506.44 -1622.94,4506.44 -1639.6,4523.11 -1656.27,4506.44 -1672.94,4506.44 -1656.27,4489.77 -1672.94,4473.11 ; -1672.94,4639.77 -1639.6,4606.44 -1606.27,4639.77 -1639.6,4673.11 -1672.94,4639.77 ; -1672.94,4906.44 -1639.6,4923.11 -1606.27,4906.44 -1622.94,4939.77 -1606.27,4973.11 -1639.6,4956.44 -1672.94,4973.11 -1656.27,4939.77 -1672.94,4906.44 ; -1672.94,5056.44 -1606.27,5056.44 -1606.27,5123.11 -1672.94,5123.11 -1672.94,5056.44 ; -1659.6,4169.77 -1619.6,4169.77 -1619.6,4209.77 -1659.6,4209.77 -1659.6,4169.77
  lines w15: -1732.73,3961.44 4825.44,3961.44 ; -1732.73,5161.44 4825.44,5161.44 ; -1181.85,3811.44 -1181.85,5311.44 ; -582.01,3811.44 -582.01,5311.44 ; 537.66,3811.44 537.66,5311.44 ; 1043.54,3811.44 1043.54,5311.44 ; 2377.15,3811.44 2377.15,5311.44 ; 3710.75,3811.44 3710.75,5311.44 ; -1732.73,3811.44 4825.44,3811.44 4825.44,5311.44 -1732.73,5311.44 -1732.73,3811.44
  text "Symbol" at -1642.73,5206.44 h72
  text "Count" at -1136.85,5206.44 h72
  text "Hole Size" at -537.01,5206.44 h72
  text "Plated" at 582.66,5206.44 h72
  text "Hole Tolerance (+)" at 1088.54,5206.44 h72
  text "Hole Tolerance (-)" at 2422.15,5206.44 h72
  text "Hole Length" at 3755.75,5206.44 h72
  text "2" at -1136.85,5056.44 h60
  text "23.62mil (0.600mm)" at -537.01,5056.44 h60
  text "PTH" at 582.66,5056.44 h60
  text "51.18mil (1.300mm)" at 3755.75,5056.44 h60
  text "2" at -1136.85,4906.44 h60
  text "33.47mil (0.850mm)" at -537.01,4906.44 h60
  text "NPTH" at 582.66,4906.44 h60
  text "-" at 3755.75,4906.44 h60
  text "2" at -1136.85,4756.44 h60
  text "33.47mil (0.850mm)" at -537.01,4756.44 h60
  text "PTH" at 582.66,4756.44 h60
  text "-" at 3755.75,4756.44 h60
  text "3" at -1136.85,4606.44 h60
  text "118.11mil (3.000mm)" at -537.01,4606.44 h60
  text "PTH" at 582.66,4606.44 h60
  text "-" at 3755.75,4606.44 h60
  text "24" at -1136.85,4456.44 h60
  text "27.56mil (0.700mm)" at -537.01,4456.44 h60
  text "PTH" at 582.66,4456.44 h60
  text "-" at 3755.75,4456.44 h60
  text "26" at -1136.85,4306.44 h60
  text "40.00mil (1.016mm)" at -537.01,4306.44 h60
  text "PTH" at 582.66,4306.44 h60
  text "-" at 3755.75,4306.44 h60
  text "82" at -1136.85,4156.44 h60
  text "8.00mil (0.203mm)" at -537.01,4156.44 h60
  text "PTH" at 582.66,4156.44 h60
  text "-" at 3755.75,4156.44 h60
  text "288" at -1136.85,4006.44 h60
  text "8.00mil (0.203mm)" at -537.01,4006.44 h60
  text "PTH" at 582.66,4006.44 h60
  text "3.00mil (0.076mm)" at 1088.54,4006.44 h60
  text "3.00mil (0.076mm)" at 2422.15,4006.44 h60
  text "-" at 3755.75,4006.44 h60
  text "429 Total" at -1136.85,3856.44 h60
  text "Slot definitions :" at -1642.73,3711.47 h60
  text "Routed Path Length" at -610.04,3711.47 h60
  text "= Calculated from tool start centre position to tool end centre position." at 492.63,3711.47 h60
  text "Hole Length" at -610.04,3611.49 h60
  text "= Routed Path Length + Tool Size = Slot length as defined in the PCB layout" at 82.76,3611.49 h60
  text ".Layer_Name" at -1267.26,-2351.64 h60
M17 Embedded Cavity:
  text ".Layer_Name" at -1267.26,-2351.64 h60
M18 Embedded Assembly:
  text ".Layer_Name" at -1252.74,-2340.54 h60
M19 Embedded Keepout:
  text ".Layer_Name" at -1164.78,-2348.54 h60
Radome cover:
  lines w0.5: 1351,340.08 1388.5,340.08 ; 1351,340.08 1351,342.58 ; 1351,340.08 1388.5,340.08 ; 1351,340.08 1351,342.58 ; 1351,342.58 1352,342.58 ; 1351,342.58 1352,342.58 ; 1351,342.58 1351,377.58 ; 1351,342.58 1352,342.58 ; 1351,342.58 1352,342.58 ; 1351,342.58 1351,377.58 ; 1351,377.58 1352,377.58 ; 1351,377.58 1352,377.58 ; 1351,377.58 1351,381.08 ; 1351,377.58 1352,377.58 ; 1351,377.58 1352,377.58 ; 1351,377.58 1351,381.08 ; 1351,381.08 1388.5,381.08 ; 1351,381.08 1388.5,381.08 ; 1352,342.58 ccw(c1353.5,342.58) 1355,342.58 ; 1352,342.58 cw(c1353.5,342.58) 1354.56,343.64 ; 1352,342.58 ccw(c1353.5,342.58) 1355,342.58 ; 1352,342.58 cw(c1353.5,342.58) 1354.56,343.64 ; 1352,377.58 ccw(c1353.5,377.58) 1355,377.58 ; 1352,377.58 cw(c1353.5,377.58) 1355,377.58 ; 1352,377.58 ccw(c1353.5,377.58) 1355,377.58 ; 1352,377.58 cw(c1353.5,377.58) 1355,377.58 ; 1354.56,343.64 cw(c1353.5,342.58) 1355,342.58 ; 1354.56,343.64 cw(c1353.5,342.58) 1355,342.58 ; 1354.56,343.64 1356,345.08 ; 1354.56,343.64 1356,345.08 ; 1354.56,343.64 1356,345.08 ; 1354.56,343.64 1356,345.08 ; 1356,345.08 1386,345.08 ; 1356,345.08 1356,375.08 ; 1356,345.08 1386,345.08 ; 1356,345.08 1356,375.08 ; 1356,375.08 1386,375.08 ; 1356,375.08 1386,375.08 ; 1386,345.08 1386,375.08 ; 1386,345.08 1386,375.08 ; 1388.5,340.08 1392,340.08 ; 1388.5,340.08 1388.5,341.08 ; 1388.5,340.08 1388.5,341.08 ; 1388.5,340.08 1392,340.08 ; 1388.5,340.08 1388.5,341.08 ; 1388.5,340.08 1388.5,341.08 ; 1388.5,341.08 ccw(c1388.5,342.58) 1390,342.58 ; 1388.5,341.08 cw(c1388.5,342.58) 1390,342.58 ; 1388.5,341.08 ccw(c1388.5,342.58) 1390,342.58 ; 1388.5,341.08 cw(c1388.5,342.58) 1390,342.58 ; 1388.5,379.08 ccw(c1388.5,377.58) 1390,377.58 ; 1388.5,379.08 cw(c1388.5,377.58) 1390,377.58 ; 1388.5,379.08 ccw(c1388.5,377.58) 1390,377.58 ; 1388.5,379.08 cw(c1388.5,377.58) 1390,377.58 ; 1388.5,379.08 1388.5,381.08 ; 1388.5,379.08 1388.5,381.08 ; 1388.5,379.08 1388.5,381.08 ; 1388.5,379.08 1388.5,381.08 ; 1388.5,381.08 1392,381.08 ; 1388.5,381.08 1392,381.08 ; 1392,340.08 1392,381.08 ; 1392,340.08 1392,381.08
